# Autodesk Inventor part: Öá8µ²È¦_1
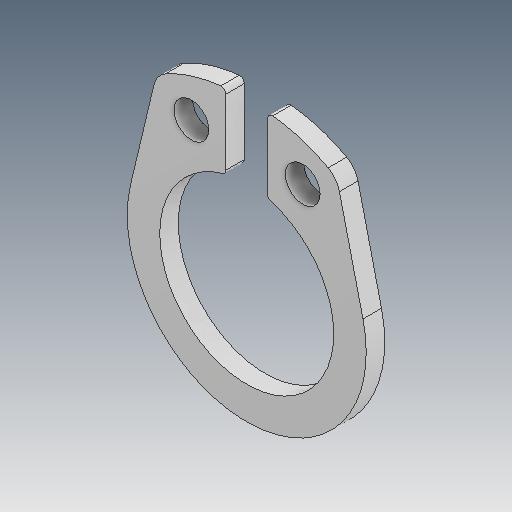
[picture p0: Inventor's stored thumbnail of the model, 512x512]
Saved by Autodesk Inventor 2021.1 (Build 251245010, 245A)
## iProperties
Created: 2021-05
Part Number: Öá8µ²È¦_1
Material: Ogólny
Document SubType Name: Modeling
Designer: user
Density: 1 g/cm^3
Appearance: Domyślna
Author: user
Revision Number: ÈÎºÎ
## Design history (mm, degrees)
feature "ÊäÈë1"
node "Bryła1"
